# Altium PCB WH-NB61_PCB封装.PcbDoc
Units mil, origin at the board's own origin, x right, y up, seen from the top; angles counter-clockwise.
Board outline 768.5 x 670.63 mil, 5 copper layers (L0, L1-Top Layer, L2, L3, L5); 1 components, 0 nets, 40 pads, 0 vias.
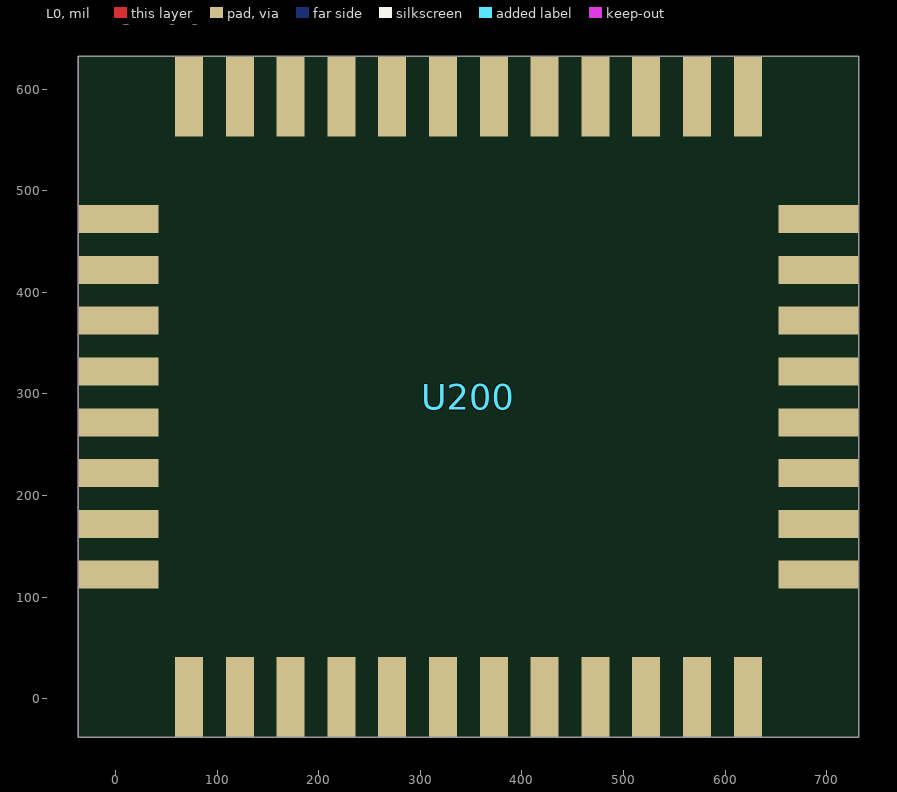
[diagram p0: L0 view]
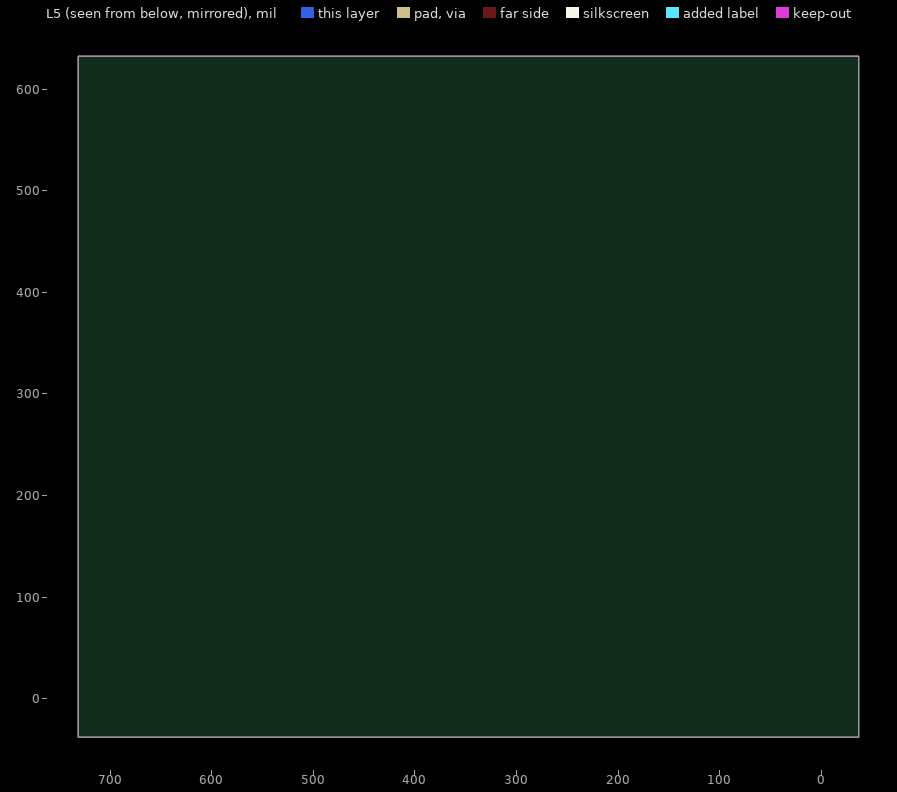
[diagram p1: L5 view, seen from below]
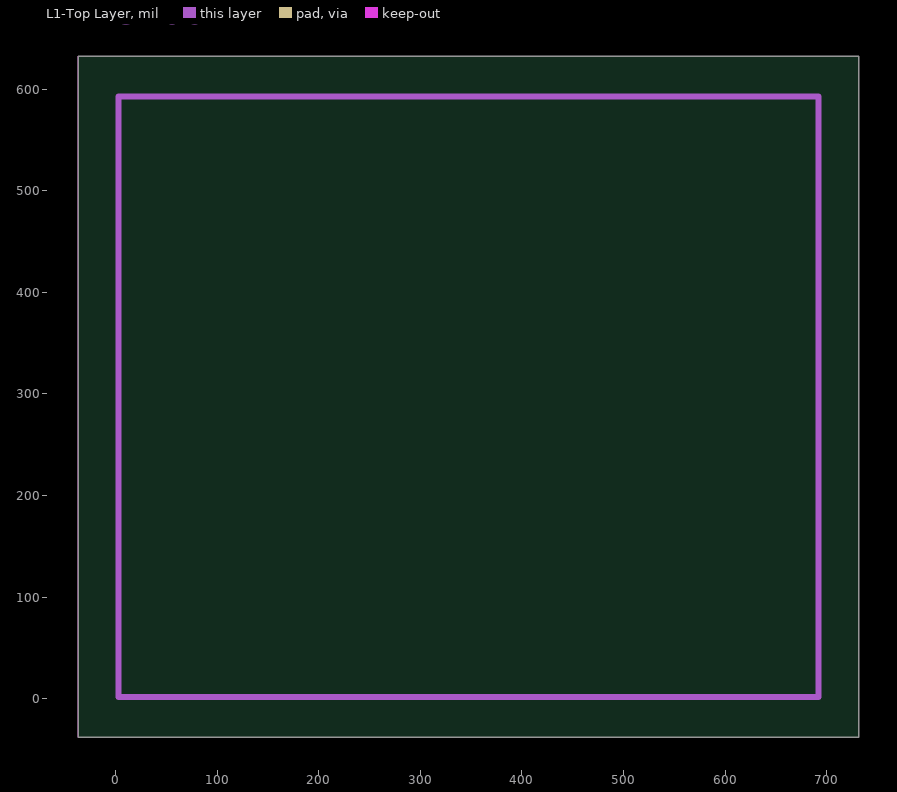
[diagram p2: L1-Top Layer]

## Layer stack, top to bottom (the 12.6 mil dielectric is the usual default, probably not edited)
L20 (Multiple PADS layers...): solder mask 0.4, Solder Resist, Dk 3.5
L0: signal copper 1.4
Dielectric 1: dielectric 12.6, FR-4, Dk 4.8
L1-Top Layer: signal copper 1.4
Dielectric2: dielectric 12.6, FR-4, Dk 4.8
L2: signal copper 1.4
Dielectric3: dielectric 12.6, FR-4, Dk 4.8
L3: signal copper 1.4
Dielectric4: dielectric 12.6, FR-4, Dk 4.8
L5: signal copper 1.4
L27-Assembly Drawing Top (Multiple PADS layers...): solder mask 0.4, Solder Resist, Dk 3.5

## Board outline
-36.93,632.49 731.57,632.49 731.57,-38.14 -36.93,-38.14

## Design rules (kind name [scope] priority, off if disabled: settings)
Clearance "Clearance - Default - DEFAULT- SMD" [IsVia vs IsSMTPin] p1: gap=0 ignorepadtopadclearanceinfootprint=FALSE
Clearance "Clearance - Default - DEFAULT - Via" [IsVia vs IsVia] p2: gap=0 ignorepadtopadclearanceinfootprint=FALSE
Clearance "Clearance - Default - DEFAULT - Net" [All] p3: gap=3 ignorepadtopadclearanceinfootprint=FALSE except(0: Arc-Hole Track-Hole SMDPad-Hole THPad-Hole Via-Hole Fill-Hole Poly-Hole Region-Hole Text-Hole; 3.94: SMDPad-Fill SMDPad-Poly SMDPad-Region THPad-Fill THPad-Poly THPad-Region Via-Fill Via-Poly Via-Region; 10: Text-Text)
ComponentClearance "ComponentClearance - Default - _1" [All] p1: gap=0 collisioncheckmode=3 verticalgap=10 showdistances=FALSE
ComponentClearance "ComponentClearance - Default -" [All] p2: gap=0 collisioncheckmode=3 verticalgap=10 showdistances=FALSE
ComponentClearance "ComponentClearance - Default - DEFAULT" [All] p3: gap=0 collisioncheckmode=3 verticalgap=10 showdistances=FALSE
FanoutControl Fanout_LCC [IsLCC] p1: bgadir=Out bgaviamode=Centered fanoutstyle=Auto fanoutdirection=Alternating viagrid=1 // Fanout_LCC (Default Rule)
FanoutControl Fanout_BGA [IsBGA] p2: bgadir=Out bgaviamode=Centered fanoutstyle=Auto fanoutdirection=Alternating viagrid=1 // Fanout_BGA (Default Rule)
FanoutControl Fanout_Small [(CompPinCount < 5)] p3: bgadir=Out bgaviamode=Centered fanoutstyle=Auto fanoutdirection=OutThenIn viagrid=1 // Fanout_Small (Default Rule)
FanoutControl Fanout_SOIC [IsSOIC] p4: bgadir=Out bgaviamode=Centered fanoutstyle=Auto fanoutdirection=Alternating viagrid=1 // Fanout_SOIC (Default Rule)
HoleToHoleClearance "HoleToHoleClearance - Default - DEFAULT" [All] p1: gap=0 allowstackedmicrovias=TRUE
Length "Default Length" [All] p1: maxlimit=50000 minlimit=0
MaxMinImpedance "Default Impedance" [All] p1: minimum=50.00 maximum=150.0
ParallelSegment "Default Parallel Segment Same Layer" [All] p1: limit=1000 gap=200
ParallelSegment "Default Parallel Segment Adjasent" [All] p2: limit=1000 gap=200
PlaneConnect "Default PlaneConnect" [All] p1: planeconnectstyle=Direct reliefexpansion=20 reliefentries=4 reliefconductorwidth=11.81 reliefairgap=10
PolygonConnect "PolygonConnect - Default SMT" [IsSMTPin] p1: connectstyle=Direct reliefconductorwidth=9.84 reliefentries=4 polygonreliefangle="45 Angle" airgapwidth=10
PolygonConnect "PolygonConnect - Default Pad" [All] p2: connectstyle=Direct reliefconductorwidth=11.81 reliefentries=4 polygonreliefangle="45 Angle" airgapwidth=10
RoutingLayers "RoutingLayers - Default - DEFAULT" [All] p1: top layer_v5=FALSE mid layer 1_v5=FALSE mid layer 2_v5=FALSE mid layer 3_v5=FALSE bottom layer_v5=FALSE
RoutingPriority "RoutingPriority - Default - DEFAULT" [All] p1: routingpriority=3
RoutingTopology "Default Routing Topology" [All] p1: topology=Shortest
RoutingVias [All] p1: holewidth=28 width=50 viastyle="Through Hole" minholewidth=28 minwidth=50 maxholewidth=28 maxwidth=50
SMDToCorner "SMDToCorner - Default - DEFAULT" [All] p1: distance=0
SolderMaskExpansion [All] p1: expansion=4
Width "Default Width" [All] p1: maxlimit=78.74 minlimit=3 preferedwidth=3.94
Width "Default Width_1" [All] p2: maxlimit=78.74 minlimit=2.99 preferedwidth=3
20 further rules are at their usual default settings.

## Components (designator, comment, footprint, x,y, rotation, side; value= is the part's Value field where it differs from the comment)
U200 "WH-NB61_I$2F$O" WH-NB61_I$2F$O 691.8,592.49 r0 top

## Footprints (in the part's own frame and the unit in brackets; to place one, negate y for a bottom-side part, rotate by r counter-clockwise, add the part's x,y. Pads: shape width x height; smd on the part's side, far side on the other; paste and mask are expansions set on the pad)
WH-NB61_I$2F$O [mm]
  rect 0.7x2 smd: 1(-1.765,0) 2(-3.035,0) 3(-4.305,0) 4(-5.575,0) 5(-6.845,0) 6(-8.115,0) 7(-9.385,0) 8(-10.655,0) 9(-11.925,0) 10(-13.195,0) 11(-14.465,0) 12(-15.735,0) 21(-15.735,-15.01) 22(-14.465,-15.01) 23(-13.195,-15.01) 24(-11.925,-15.01) 25(-10.655,-15.01) 26(-9.385,-15.01) 27(-8.115,-15.01) 28(-6.845,-15.01) 29(-5.575,-15.01) 30(-4.305,-15.01) 31(-3.035,-15.01) 32(-1.765,-15.01)
  rect 2x0.7 smd: 13(-17.5,-3.06) 14(-17.5,-4.33) 15(-17.5,-5.6) 16(-17.5,-6.87) 17(-17.5,-8.14) 18(-17.5,-9.41) 19(-17.5,-10.68) 20(-17.5,-11.95) 33(0,-11.95) 34(0,-10.68) 35(0,-9.41) 36(0,-8.14) 37(0,-6.87) 38(0,-5.6) 39(0,-4.33) 40(0,-3.06)
  L1-Top Layer lines w0.15: -17.5,-15.01 -17.5,0 0,0 0,-15.01 -17.5,-15.01

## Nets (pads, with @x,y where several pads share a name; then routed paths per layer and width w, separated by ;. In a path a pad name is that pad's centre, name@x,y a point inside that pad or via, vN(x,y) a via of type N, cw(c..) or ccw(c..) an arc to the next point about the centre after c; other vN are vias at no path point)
pads on no net: U200.1 U200.2 U200.3 U200.4 U200.5 U200.6 U200.7 U200.8 U200.9 U200.10 U200.11 U200.12 U200.13 U200.14 U200.15 U200.16 U200.17 U200.18 U200.19 U200.20 U200.21 U200.22 U200.23 U200.24 U200.25 U200.26 U200.27 U200.28 U200.29 U200.30 U200.31 U200.32 U200.33 U200.34 U200.35 U200.36 U200.37 U200.38 U200.39 U200.40

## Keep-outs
Keep-Out Layer:
  the board outline again, w0.04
